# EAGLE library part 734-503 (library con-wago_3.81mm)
Serie 734, Federleiste mit geraden Einlötstiften / Series 734, Female connector with straight solder pins Polzahl / Pole No.: 3 Bemessungsspannung / Rated Voltage: 160 V Nennstrom / Nominal Current: 10 A Lötstiftlänge: / Solder Pin Length: 3.8 mm Farbe / Color: orange / orange Stand: 01.01.2012. Die jeweils aktuellen Daten zu diesem Artikel finden Sie in unserem Produktkatalog, den Sie unter www.wago.com einsehen können. As of: 01/01/2012. Please find the newest data for this article in our product catalogue, which can be viewed under www.wago.com.
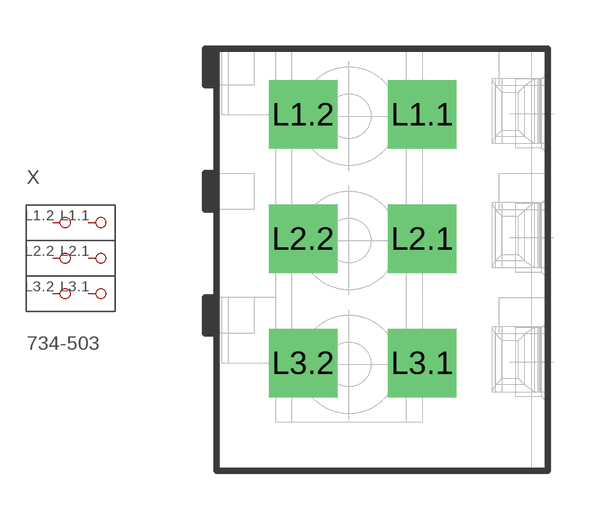
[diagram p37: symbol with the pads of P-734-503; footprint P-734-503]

Designator prefix X

## 734-503  [P-734-503]
L1.1  P1.1
L1.2  P1.2
L2.1  P2.1
L2.2  P2.2
L3.1  P3.1
L3.2  P3.2

## Footprint P-734-503 (pad centres in mm)
drill 1.4 square: L1.1 1.309,4.455; L1.2 -2.341,4.455; L2.1 1.309,0.645; L2.2 -2.341,0.645; L3.1 1.309,-3.165; L3.2 -2.341,-3.165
